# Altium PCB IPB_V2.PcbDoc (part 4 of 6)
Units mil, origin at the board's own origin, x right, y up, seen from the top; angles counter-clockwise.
Board outline 14000 x 12000 mil, 6 copper layers (Top, L2 - Plane/Horiz, L3 - Horiz, L4 - Vert, L5 - Plane/Horiz, Bottom), stack 61.468 mil thick; 657 components, 436 nets, 1897 pads, 873 vias.
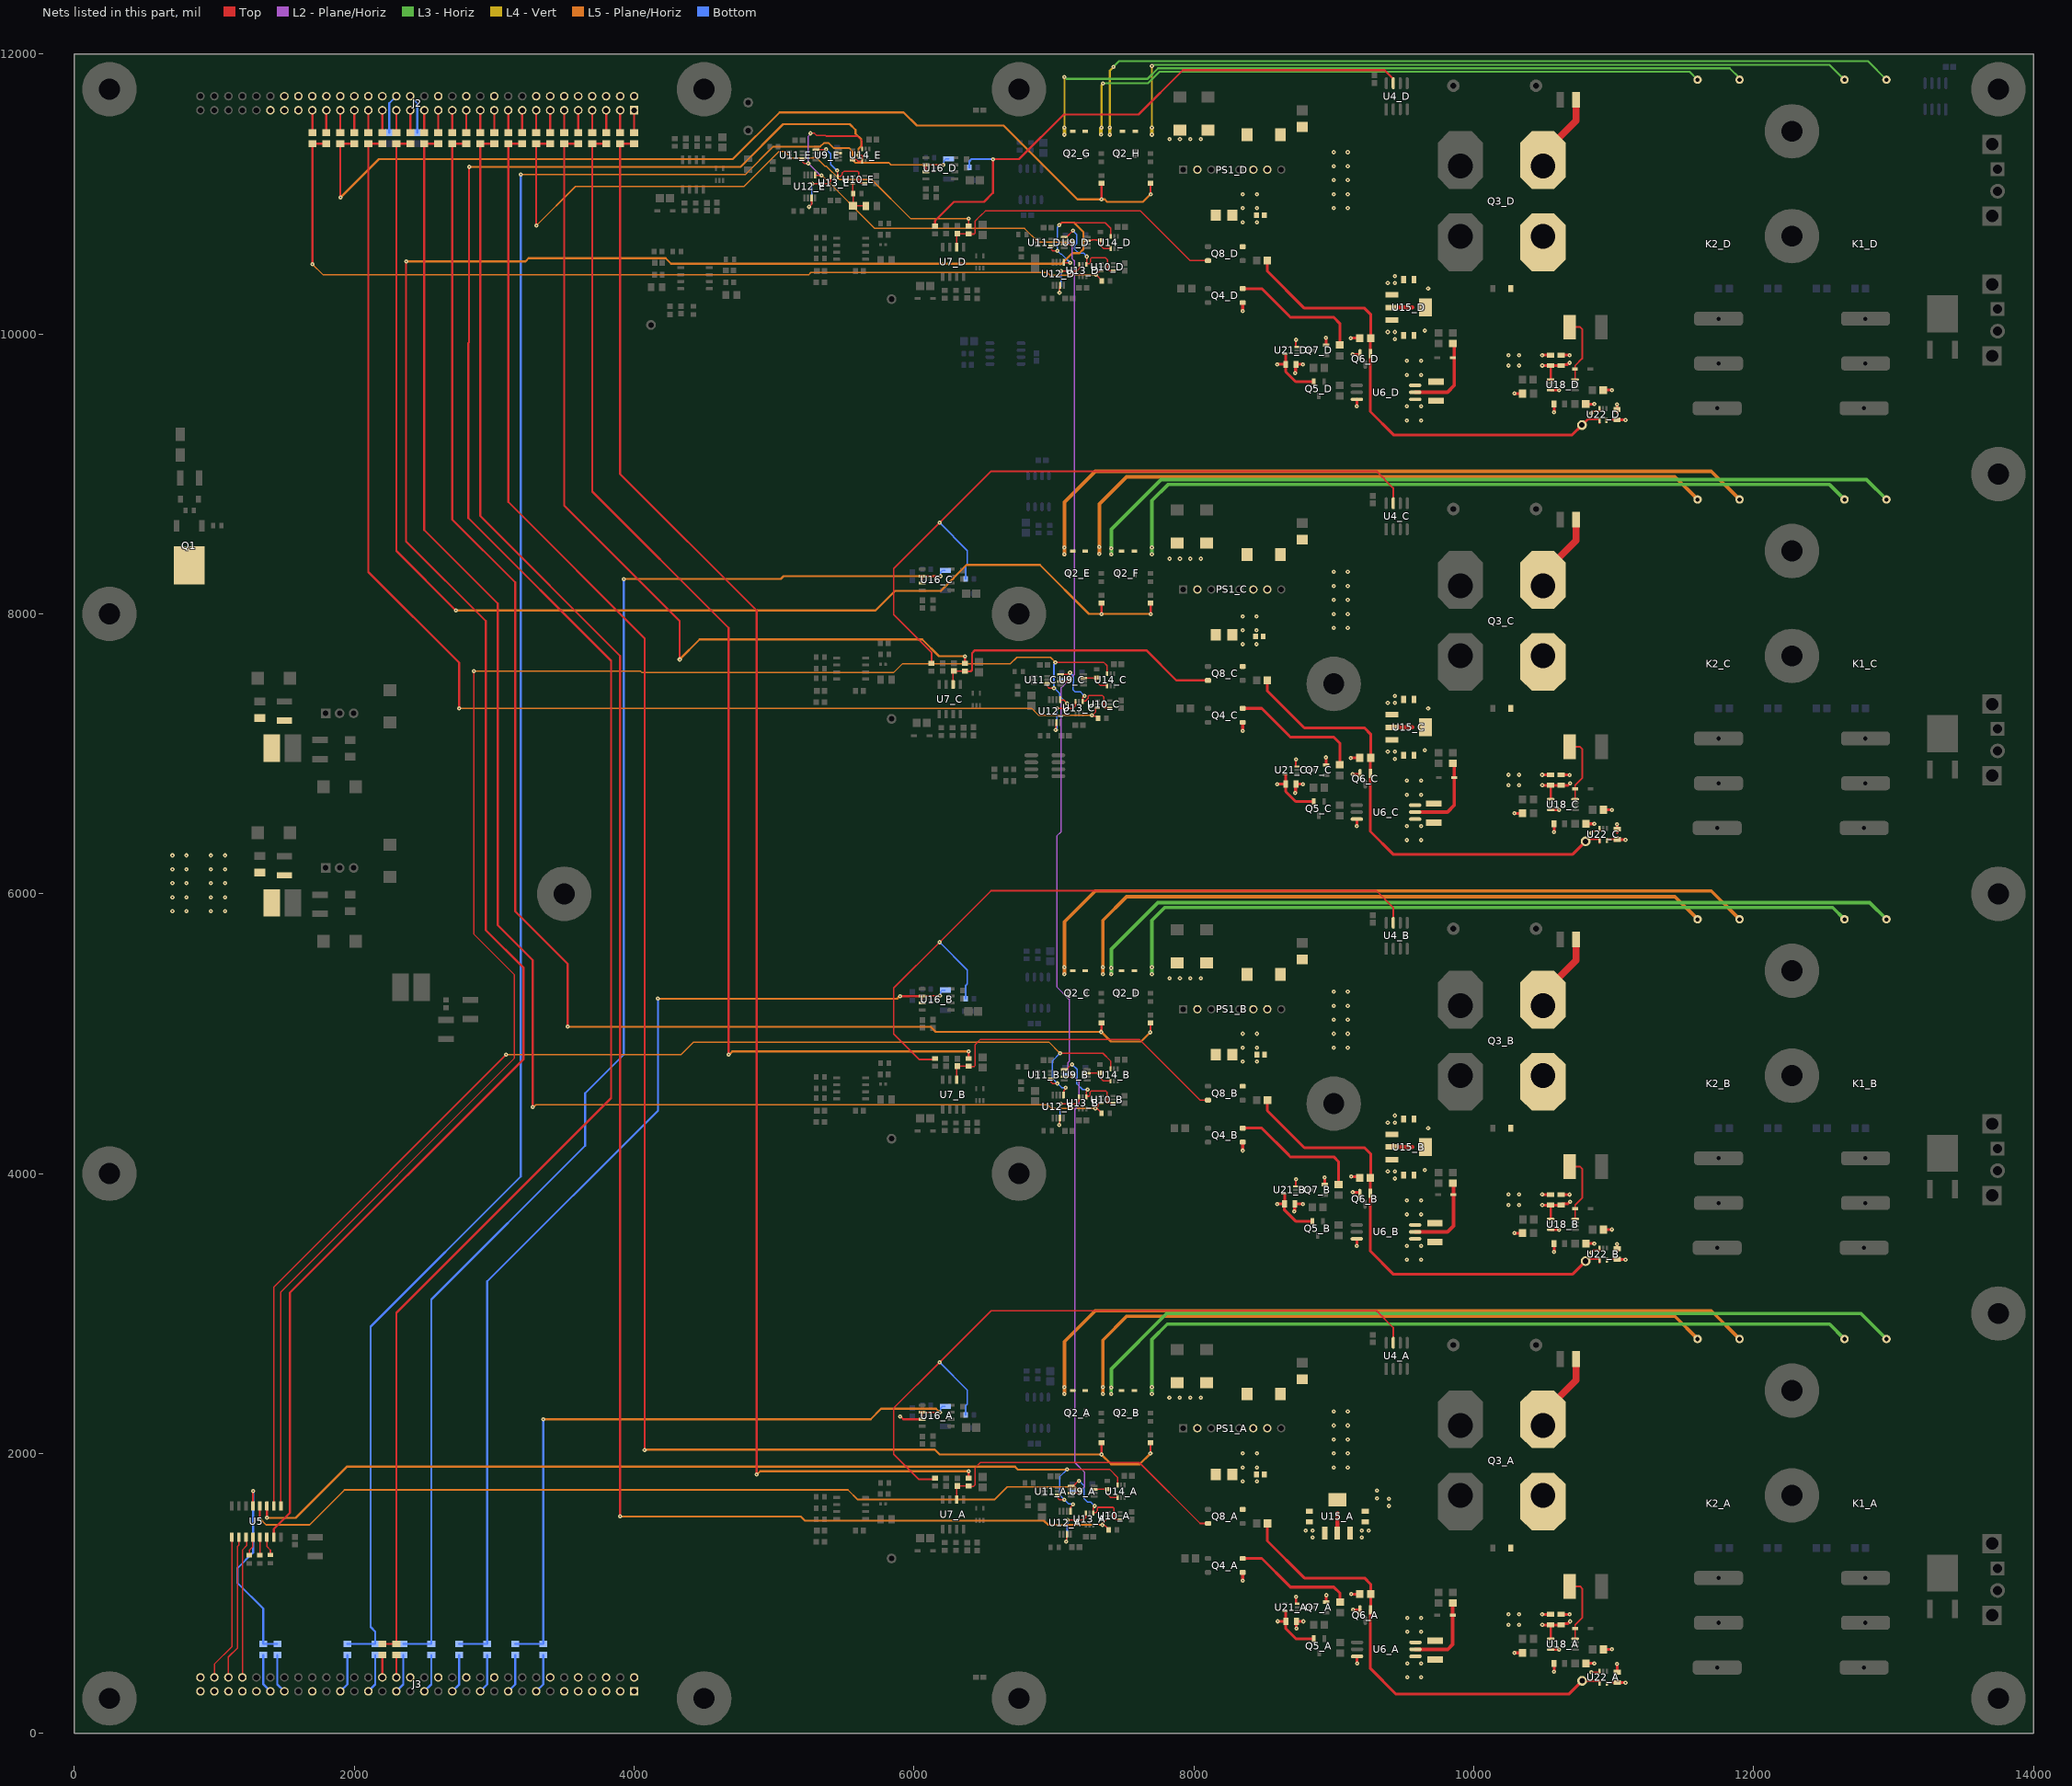
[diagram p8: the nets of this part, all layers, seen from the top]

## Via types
v1: diameter 30, hole 10, Top to Bottom, 873 vias

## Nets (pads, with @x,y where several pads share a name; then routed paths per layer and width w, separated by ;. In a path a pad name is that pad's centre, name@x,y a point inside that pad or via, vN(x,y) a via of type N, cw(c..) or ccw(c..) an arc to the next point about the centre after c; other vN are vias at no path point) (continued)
CH-EN_A: Q4_A.4 R92_A.1 | length 861.2
  Top w20: Q4_A.4@8349.02,1250 8485,1250 8680.03,1054.97 8690,1045 9000,1045 9045,1000 R92_A.1@9045,938.39
CH-EN_B: Q4_B.4 R92_B.1 | length 934.2
  Top w20: Q4_B.4@8349.02,4325 8485,4325 8680.03,4129.97 ; 8690,4120 9000,4120 9034.76,4085.24 R92_B.1@9034.76,3922.05
CH-EN_C: Q4_C.4 R92_C.1 | length 937.7
  Top w20: Q4_C.4@8349.02,7325 8485,7325 8680.03,7129.97 ; 8690,7120 9000,7120 9043.42,7076.58 R92_C.1@9043.42,6922.05
CH-EN_D: Q4_D.4 R92_D.1 | length 937.7
  Top w20: Q4_D.4@8349.02,10325 8485,10325 8680.03,10129.97 ; 8690,10120 9000,10120 9043.42,10076.58 R92_D.1@9043.42,9922.05
CH-ENABLE_E: C2.2 R42.1 R73_E.2 U10_E.3 | length 248.2
  Top w10: R73_E.2@5561.69,11011.22 U10_E.3@5561.69,11079.41 ; R73_E.2@5565.47,11005 5565.47,10916.89 C2.2@5565,10916.42 5654.21,10916.42 R42.1@5655.63,10915
CH-ENABLEBUF_A: U9_A.1 U10_A.4 U13_A.1 | length 661.3
  Top w10: U9_A.1@7123.31,1768.39 7139.06,1768.39 7175.67,1805 v1(7180,1805) ; U13_A.1@7280.59,1573.31 U13_A.1@7280.59,1575.13 ; v1(7290,1625) 7290,1619.59 7280.59,1610.18 7280.59,1580.87 7283.46,1578 7300,1578 7309,1587 7309,1609.14 7314.86,1615 7422.17,1615 7430,1607.17 7430,1535.32 7435.91,1529.41 U10_A.4@7473.31,1529.41
  Bottom w10: v1(7180,1805) 7215.32,1769.68 7215.32,1709.32 7213.99,1707.99 7213.99,1678.43 7238.8,1653.63 7261.37,1653.63 v1(7290,1625)
CH-ENABLEBUF_B: U9_B.1 U10_B.4 U13_B.1 | length 668.6
  Top w10: U9_B.1@7073.31,4743.39 7089.06,4743.39 7125.67,4780 v1(7130,4780) ; U13_B.1@7230.59,4548.31 U13_B.1@7230.59,4550.13 ; v1(7240,4600) 7240,4594.59 7230.59,4585.18 7230.59,4555.87 7233.46,4553 7250,4553 7259,4562 7259,4584.14 7264.86,4590 7372.17,4590 7380,4582.17 7380,4510.31 7385.91,4504.41 U10_B.4@7423.31,4504.41
  Bottom w10: v1(7130,4780) 7165.32,4744.68 7165.32,4684.32 7163.99,4682.99 7163.99,4641.01 7205,4600 v1(7240,4600)
CH-ENABLEBUF_C: U9_C.1 U10_C.4 U13_C.1 | length 646
  Top w10: U9_C.1@7048.31,7568.39 7097.97,7568.39 7109.59,7580 v1(7115,7580) ; U13_C.1@7205.59,7373.31 U13_C.1@7205.59,7375.13 ; v1(7218.42,7414.09) 7216.07,7414.09 7205.59,7403.62 7205.59,7380.87 7208.46,7378 7225,7378 7245,7398 7245,7412.14 7250.86,7418 7344.17,7418 7355,7407.17 7355,7335.32 7360.91,7329.41 U10_C.4@7398.31,7329.41
  Bottom w10: v1(7115,7580) 7140.32,7554.68 7140.32,7503.92 7135,7498.6 7135,7459.77 7152.93,7441.84 7190.68,7441.84 v1(7218.42,7414.09)
CH-ENABLEBUF_D: U9_D.1 U10_D.4 U13_D.1 | length 697.5
  Top w10: U9_D.1@7074.84,10693.39 7090.59,10693.39 7135,10737.79 v1(7135,10740) ; U13_D.1@7232.13,10498.31 U13_D.1@7232.13,10500.13 ; v1(7235.83,10554) 7233.98,10552.15 7233.98,10504.02 7235,10503 7251.54,10503 7260.54,10512 7260.54,10537.14 7269.39,10546 7367.7,10546 7381.54,10532.17 7381.54,10460.32 7387.44,10454.41 U10_D.4@7424.84,10454.41
  Bottom w10: v1(7135,10740) 7161.18,10713.82 7161.18,10645.21 7147.91,10631.95 7147.91,10607.09 7176.66,10578.35 7213.48,10578.35 7220.55,10571.28 7220.55,10569.28 v1(7235.83,10554)
CH-ENABLEBUF_E: U9_E.1 U10_E.4 U13_E.1 | length 593.1
  Top w10: U9_E.1@5298.31,11318.39 5299.11,11319.19 5372.07,11319.19 v1(5372.87,11320) ; v1(5449.14,11170) 5452.87,11166.26 5452.87,11133.59 5458.46,11128 5475,11128 5487.98,11140.98 5487.98,11152.33 5500.76,11165.12 5597.05,11165.12 5605,11157.17 5605,11085.32 5610.91,11079.41 U10_E.4@5648.31,11079.41
  Bottom w10: v1(5372.87,11320) 5405,11287.87 5405,11212.57 5447.57,11170 v1(5449.14,11170)
CH-ENABLEn_A: R74_A.2 U9_A.7 U14_A.1 | length 210.4
  Top w10: U9_A.7@7286.69,1742.8 7288.42,1744.53 7322.1,1744.53 7322.57,1745 7375.12,1745 7377.32,1742.8 7377.32,1712.72 7403.35,1686.69 U14_A.1@7454.41,1686.69
CH-ENABLEn_B: R74_B.2 U9_B.7 U14_B.1 | length 210.4
  Top w10: U9_B.7@7236.69,4717.8 7238.42,4719.53 7272.1,4719.53 7272.57,4720 7325.12,4720 7327.32,4717.8 7327.32,4687.72 7353.35,4661.69 U14_B.1@7404.41,4661.69
CH-ENABLEn_C: R74_C.2 U9_C.7 U14_C.1 | length 207.2
  Top w10: U9_C.7@7211.69,7542.8 R74_C.2@7302.32,7542.8 ; R74_C.2@7305,7545.47 7305,7515 7331.92,7488.08 7378.02,7488.08 U14_C.1@7379.41,7486.69
CH-ENABLEn_D: R74_D.2 U9_D.7 U14_D.1 | length 217.6
  Top w10: U9_D.7@7238.23,10667.8 7239.96,10669.53 7267.91,10669.53 7273.29,10674.92 7297.49,10674.92 7300.11,10672.29 7329.71,10672.29 R74_D.2@7331.54,10670.47 7331.54,10635.04 7354.88,10611.69 U14_D.1@7405.94,10611.69
CH-ENABLEn_E: U9_E.7
CH-I_A: R69_A.1 R79_A.1 U4_A.7 | length 5183.4
  Top w12: R69_A.1@6150,1822.56 6142.44,1815 6035,1815 5855,1995 5855,2325 v1(6182.13,2652.13) 6550,3020 9305,3020 9425,2900 U4_A.7@9425,2791.11
  Bottom w12: v1(6182.13,2652.13) 6381,2453.25 6381,2353.92 6369.68,2342.61 R79_A.1@6369.68,2275
CH-I_B: R69_B.1 R79_B.1 U4_B.7 | length 5210.3
  Top w12: R69_B.1@6150,4824.51 6142.44,4816.95 6035,4816.95 5855,4996.95 5855,5326.95 v1(6182.13,5654.07) 6550,6021.95 9305,6021.95 9425,5901.95 U4_B.7@9425,5793.06
  Bottom w12: v1(6182.13,5654.07) 6381,5455.2 6381,5355.87 6369.68,5344.55 R79_B.1@6369.68,5250
CH-I_C: R69_C.1 R79_C.1 U4_C.7 | length 5294.9
  Top w12: R69_C.1@6125,7647.56 6125,7725 5855,7995 5855,8325 v1(6182.13,8652.13) 6550,9020 9305,9020 9425,8900 U4_C.7@9425,8791.11
  Bottom w12: v1(6182.13,8652.13) 6381,8453.25 6381,8353.92 6369.68,8342.61 R79_C.1@6369.68,8250
CH-I_D: R69_D.1 R79_D.1 U4_D.7 | length 4177.1
  Top w15: R69_D.1@6150,10772.56 6150,10810 6285,10945 6500,10945 6565,11010 v1(6565,11250) 6750,11250 7070,11570 7605,11570 7921.32,11886.32 9362.98,11886.32 9425,11824.3 U4_D.7@9425,11793.06
  Bottom w15: R79_D.1@6394.68,11190 6394.68,11234.68 6410,11250 v1(6565,11250)
CHA_CURRENT_SET_1: R4.1 R6.1 R66_A.1 | length 11587.9
  Top w15: R4.1@4000,11360.63 R6.1@3900,11360.63 3900,9000 4875,8025 v1(4875,1850) ; R66_A.1@6390,1822.56 v1@6390,1872.09
  L5 - Plane/Horiz w15: v1(4875,1850) 4879.06,1850 4901.62,1872.56 v1(6389.53,1872.56)
CHA_FET_EN_1: R19.1 R21.1 R73_A.2 U10_A.3 | length 13919.3
  Top w10: U10_A.3@7386.69,1529.41 7376.85,1529.41 7349.12,1501.68 7349.12,1493.83 v1(7345.29,1490) 7349.12,1486.17 7363.24,1486.17 7390.47,1458.94 R73_A.2@7390.47,1455
  Top w15: R19.1@3000,11360.63 R21.1@2900,11360.63 2900,8700 3900,7700 v1(3900,1550)
  L5 - Plane/Horiz w15: v1(3900,1550) 5191.04,1550 5221.04,1520 6928.46,1520 6958.46,1490 v1(7345.29,1490)
CHA_I_1: C38_A.1 R20.1 R22.1 U16_A.6 U16_A.7 | length 5095.8
  Top w10: U16_A.7@6059.21,2245 U16_A.6@6059.21,2295 v1(6185,2295)
  Top w15: v1(5900,2265) 5904.06,2265 5924.06,2245 U16_A.7@6059.21,2245
  L5 - Plane/Horiz w15: v1(3350,2245) 5690,2245 5765,2320 6156.97,2320 6181.97,2295 v1(6185,2295)
  Bottom w10: v1(6185,2295) 6185,2297.71 6188.79,2301.5 6188.79,2323.03 6202.61,2336.85 C38_A.1@6223.28,2336.85
  Bottom w15: R22.1@3150,638.74 R20.1@3350,638.74 v1(3350,2245)
CHA_RLY_EN_1: R3.1 R5.1 R64_A.1 R64_B.1 | length 13693.8
  Top w15: R3.1@3200,11360.63 R5.1@3100,11360.63 3100,8800 4075,7825 v1(4075,2025) ; v1(7339,1993) 7339.5,1993.5 7339.5,2076.94 R64_A.1@7340,2077.44 ; v1(7690,2000) R64_B.1@7690,2077.44
  L5 - Plane/Horiz w15: v1(4075,2025) 4077.51,2027.51 6148.46,2027.51 6182.97,1993 v1(7339,1993) 7410,1922 7612,1922 v1(7690,2000)
CHB_CURRENT_SET_1: R8.1 R10.1 R66_B.1 | length 8787.9
  Top w15: R8.1@3800,11360.63 R10.1@3700,11360.63 3700,8875 4675,7900 v1(4675,4850) ; R66_B.1@6390,4822.56 v1@6390,4872.09
  L5 - Plane/Horiz w15: v1(4675,4850) 4679.06,4850 4701.62,4872.56 v1(6389.53,4872.56)
CHB_FET_EN_1: R23.1 R25.1 R73_B.2 U10_B.3 | length 11469.8
  Top w10: U10_B.3@7336.69,4504.41 7326.85,4504.41 7317.03,4494.59 7317.03,4486.11 v1(7295.81,4464.9) 7299.64,4461.08 7313.33,4461.08 7340.47,4433.94 R73_B.2@7340.47,4430
  Top w15: R23.1@2600,11360.63 R25.1@2500,11360.63 2500,8600 3025,8075 3025,5775 3275,5525 v1(3275,4475)
  L5 - Plane/Horiz w10: v1(3275,4475) 3280.41,4475 3297.91,4492.5 6955.07,4492.5 6982.67,4464.9 v1(7295.81,4464.9)
CHB_I_1: C38_B.1 R24.1 R26.1 U16_B.6 U16_B.7 | length 7461.6
  Top w10: U16_B.7@6059.21,5220 U16_B.6@6059.21,5270 v1(6185,5270)
  Top w15: v1(5900,5267.32) 5901.34,5268.66 6057.87,5268.66 U16_B.6@6059.21,5270
  L5 - Plane/Horiz w15: v1(4170,5250) 5878.62,5250 5895.94,5267.32 v1(5900,5267.32) v1@5898.66,5268.66
  Bottom w10: v1(6185,5270) 6185,5272.71 6188.79,5276.5 6188.79,5298.03 6202.61,5311.85 C38_B.1@6223.28,5311.85
  Bottom w15: R26.1@2750,638.74 R24.1@2950,638.74 2950,3230 4170,4450 v1(4170,5250)
CHB_RLY_EN_1: R7.1 R9.1 R64_C.1 R64_D.1 | length 11120.1
  Top w15: R7.1@2800,11360.63 R9.1@2700,11360.63 2700,8675 3150,8225 3150,5875 3525,5500 v1(3525,5050) ; v1(7338,5013) 7340,5015 R64_C.1@7340,5077.44 ; v1(7688,5010) 7690,5012 R64_D.1@7690,5077.44
  L5 - Plane/Horiz w15: v1(3525,5050) 6118.46,5050 6155.46,5013 v1(7338,5013) 7407,4944 7622,4944 v1(7688,5010)
CHC_CURRENT_SET_1: R12.1 R14.1 R66_C.1 | length 6325.1
  Top w15: R12.1@3600,11360.63 R14.1@3500,11360.63 3500,8775 4325,7950 v1(4325,7675) ; R66_C.1@6365,7647.56 v1@6365,7697.09
  L5 - Plane/Horiz w15: v1(4325,7675) 4467.5,7817.5 6058.61,7817.5 6178.55,7697.56 v1(6364.53,7697.56)
CHC_FET_EN_1: R27.1 R29.1 R73_C.2 U10_C.3 | length 9077.9
  Top w10: v1(7270,7275) v1@7272.87,7275 ; U10_C.3@7311.69,7329.41 7301.85,7329.41 7298.98,7326.54 7298.98,7301.11 v1@7272.87,7275 ; R73_C.2@7315.47,7255 7315.47,7258.94 7304.72,7269.69 7280.73,7269.69 7275.41,7275 v1@7272.87,7275
  Top w15: R27.1@2200,11360.63 R29.1@2100,11360.63 2100,8300 2750,7650 v1(2750,7325)
  L5 - Plane/Horiz w10: v1(2750,7325) 6842.43,7325 6892.43,7275 v1(7270,7275)
CHC_I_1: C38_C.1 R28.1 R30.1 U16_C.6 U16_C.7 | length 10901.9
  Top w10: U16_C.7@6059.21,8220 U16_C.6@6059.21,8270 v1(6190,8270)
  L5 - Plane/Horiz w15: v1(3925,8250) 5047.5,8250 5067.5,8270 v1(6190,8270)
  Bottom w10: v1(6190,8270) 6190,8298.03 6203.82,8311.85 C38_C.1@6223.28,8311.85
  Bottom w15: R30.1@2350,638.74 R28.1@2550,638.74 2550,3100 3650,4200 3650,4575 3925,4850 v1(3925,8250)
CHC_RLY_EN_1: R11.1 R13.1 R64_E.1 R64_F.1 | length 9014
  Top w15: R11.1@2400,11360.63 R13.1@2300,11360.63 2300,8450 v1(2725,8025) ; v1(7340,8000) R64_E.1@7340,8077.44 ; R64_F.1@7690,8077.44 7691,8076.44 7691,8001 v1(7692,8000)
  L5 - Plane/Horiz w15: v1(2725,8025) 5725,8025 5865,8165 6190.96,8165 6375.96,8350 6900,8350 7250,8000 v1(7340,8000) v1(7692,8000)
CHD_CURRENT_SET_1: R16.1 R18.1 R66_D.1 | length 4244.8
  Top w10: R66_D.1@6390,10772.56 v1(6390,10824.22)
  Top w15: v1(3300,10775) R18.1@3300,11360.63 R16.1@3400,11360.63
  L5 - Plane/Horiz w10: v1(3300,10775) 3580,11055 4785,11055 5033.55,11303.55 5079.51,11303.55 5123.06,11260 5302.57,11260 5362.57,11200 5373.43,11200 5468.1,11105.33 5512.15,11105.33 5512.37,11105.12 5697.31,11105.12 5978.21,10824.22 v1(6390,10824.22)
CHD_FET_EN_1: R31.1 R34.1 R73_D.2 U10_D.3 | length 6722.2
  Top w10: U10_D.3@7338.23,10454.41 7328.39,10454.41 7300,10426.02 v1(7300,10425) 7300.94,10425 7342.01,10383.94 R73_D.2@7342.01,10380
  Top w15: v1(1700,10500) R34.1@1700,11360.63 R31.1@1800,11360.63
  L5 - Plane/Horiz w10: v1(1700,10500) 1775,10425 5248.33,10425 5263.34,10440 6952.57,10440 6972.57,10420 7094.27,10420 7099.27,10425 v1(7300,10425)
CHD_I_1: C38_D.1 R32.1 R35.1 U16_D.6 U16_D.7 | length 14618
  Top w10: U16_D.7@6084.21,11160 U16_D.6@6084.21,11210 v1(6210,11210)
  L5 - Plane/Horiz w12: v1(3190,11140) 4795,11140 4995,11340 5330,11340 5355,11365 5390,11365 5425,11330 5535,11330 5560,11305 5560,11245 5580,11225 5820,11225 5835,11210 v1(6210,11210)
  Bottom w10: v1(6210,11210) 6210,11212.71 6213.79,11216.5 6213.79,11238.03 6227.61,11251.85 C38_D.1@6248.28,11251.85
  Bottom w15: R35.1@1950,638.74 R32.1@2150,638.74 2150,726.21 2116.46,759.75 2116.46,2906.46 3190,3980 v1(3190,11140)
CHD_RLY_EN_1: R15.1 R17.1 R64_G.1 R64_H.1 | length 7008.2
  Top w15: v1(1900,10975) R17.1@1900,11360.63 R15.1@2000,11360.63 ; R64_G.1@7340,11077.44 7340.5,11076.94 7340.5,10963.5 v1(7341,10963) ; v1@7690.5,11001.5 R64_H.1@7690.5,11076.94
  L5 - Plane/Horiz w15: v1(1900,10975) 2175,11250 4705,11250 5040,11585 5925,11585 6020,11490 6640,11490 7167,10963 v1(7341,10963) 7341.66,10962.34 7362.66,10962.34 7380,10945 7636,10945 v1(7691.5,11000.5)
COIL_DRV_HIGH_A: C16_A.1 C16_B.1 C16_C.1 C16_D.1 C17_A.2 C17_B.2 C17_C.2 C17_D.2 C18_A.2 C18_B.2 C18_C.2 C18_D.2 C45.2 C55.2 D4_A.1 D4_B.1 D4_C.1 D4_D.1 D4_E.1 D4_F.1 D4_G.1 D4_H.1 K1_A.2 K1_B.2 K1_C.2 K1_D.2 K2_A.2 K2_B.2 K2_C.2 K2_D.2 L2.1 L4.1 PS1_A.2 PS1_B.2 PS1_C.2 PS1_D.2 Q1.2 R81.2 R85.2 | length 45321.5
  L3 - Horiz w15: v1(7075,11836.21) 7079.06,11836.21 7090.27,11825 7669.64,11825 7744.64,11900 11830,11900 11900,11830 K2_D.2@11900,11818 ; v1(7424.16,11908.81) 7465.36,11950 12818,11950 K1_D.2@12950,11818
  L3 - Horiz w25: v1(7409.58,2425.42) 7409.79,2425.63 7409.79,2469.79 v1(7410,2470) 7410,2605 7805,3000 12768,3000 K1_A.2@12950,2818 ; v1(7409.86,5425.07) 7409.86,5604.86 7742.2,5937.2 12830.8,5937.2 K1_B.2@12950,5818 ; v1(7410,8425) v1(7410,8470) 7409.86,8470.14 7409.86,8604.86 7765,8960 12808,8960 K1_C.2@12950,8818
  L5 - Plane/Horiz w25: v1(7075,2425) v1(7075,2475) 7075,2800 7295,3020 11698,3020 K2_A.2@11900,2818 ; v1(7075,5425) v1(7075,5475) 7075,5800 7295,6020 11698,6020 K2_B.2@11900,5818 ; v1(7075,8425) v1(7075,8475) 7075,8800 7295,9020 11698,9020 K2_C.2@11900,8818
  L4 - Vert w15: v1(7075,11475) v1(7075,11836.21) ; v1(7398.66,11476.26) 7398.66,11881.27 7424.16,11906.77 v1(7424.16,11908.81)
  L4 - Vert w25: v1(7075,11425) v1(7075,11475) ; v1(7398.66,11476.26) 7399.33,11475.59 7399.33,11425.67 v1(7400,11425)
  other v1: 7825,2400 7900,2400 7975,2400 8050,2400 7825.39,5394.88 7900.39,5394.88 7975.39,5394.88 8050.39,5394.88 7409.86,5470 700,5875 800,5875 975,5875 1075,5875 700,5975 800,5975 975,5975 1075,5975 700,6075 800,6075 975,6075 1075,6075 700,6175 800,6175 975,6175 1075,6175 700,6275 800,6275 975,6275 1075,6275 7825.39,8394.88 7900.39,8394.88 7975.39,8394.88 8050.39,8394.88 7825.39,11394.88 7900.39,11394.88 7975.39,11394.88 8050.39,11394.88
COIL_RTN_HIGH_A: D4_B.2 K1_A.5 Q2_B.2 | length 5429.9
  L3 - Horiz w25: v1(7700,2425) v1(7700,2475) 7700,2815 7810,2925 12543,2925 K1_A.5@12650,2818
COIL_RTN_HIGH_B: D4_D.2 K1_B.5 Q2_D.2 | length 5408.1
  L3 - Horiz w25: v1(7700,5425) v1(7700,5475) 7700,5810 7792.2,5902.2 12565.8,5902.2 K1_B.5@12650,5818
COIL_RTN_HIGH_C: D4_F.2 K1_C.5 Q2_F.2 | length 5427
  L3 - Horiz w25: v1(7700,8425) v1(7700,8475) 7700,8810 7815,8925 12543,8925 K1_C.5@12650,8818
COIL_RTN_HIGH_D: D4_H.2 K1_D.5 Q2_H.2 | length 5489.9
  L3 - Horiz w15: v1(7700,11917.5) 7704.06,11917.5 7711.56,11925 12543,11925 K1_D.5@12650,11818
  L4 - Vert w15: v1(7700,11475) v1(7700,11917.5)
  L4 - Vert w25: v1(7700,11425) v1(7700,11475)
COIL_RTN_LOW_A: D4_A.2 K2_A.5 Q2_A.2 | length 4772.5
  L5 - Plane/Horiz w25: v1(7350,2425) v1(7350,2475) 7350,2810 7520,2980 11438,2980 K2_A.5@11600,2818
COIL_RTN_LOW_B: D4_C.2 K2_B.5 Q2_C.2 | length 4772.5
  L5 - Plane/Horiz w25: v1(7350,5425) v1(7350,5475) 7350,5810 7520,5980 11438,5980 K2_B.5@11600,5818
COIL_RTN_LOW_C: D4_E.2 K2_C.5 Q2_E.2 | length 4777.9
  L5 - Plane/Horiz w25: v1(7325,8429.97) 7325,8785 7520,8980 11438,8980 K2_C.5@11600,8818
  other v1: 7325,8479.97
COIL_RTN_LOW_D: D4_G.2 K2_D.5 Q2_G.2 | length 4680.1
  L3 - Horiz w15: v1(7350,11792.5) 7672.5,11792.5 7755,11875 11543,11875 K2_D.5@11600,11818
  L4 - Vert w15: v1(7339.53,11475) 7339.53,11777.97 7350,11788.44 v1(7350,11792.5)
  L4 - Vert w25: v1(7335.96,11425.96) 7335.96,11470.08 7339.53,11473.65 v1(7339.53,11475)
DIO_SPARE_0_3: J2.2
DIO_SPARE_1_3: J2.4
DIO_SPARE_2_3: J2.6
DIO_SPARE_3_3: J2.8
DIO_SPARE_4_3: J2.10
DIO_SPARE_5_3: J2.12
DIO_SPARE_6_3: J2.14
DIO_SPARE_7_3: J2.16
FAULT-BUF_A: Q6_A.1 R83_A.2 R90_A.2 TP5_A.1 U22_A.4 | length 3358.4
  Top w15: TP5_A.1@10775,375 10898.78,375 10899.41,374.37 U22_A.4@10899.41,364.53
  Top w20: R83_A.2@8526.77,1500 8525,1498.23 8525,1375 8790,1110 9220,1110 9263.39,1066.61 R90_A.2@9263.39,995 9262.89,994.51 9262.89,883.9 Q6_A.1@9262.4,883.4 9262.4,462.6 9445,280 10680,280 TP5_A.1@10775,375
FAULT-BUF_B: Q6_B.1 R83_B.2 R90_B.2 TP5_B.1 U22_B.4 | length 3415.1
  Top w15: TP5_B.1@10800,3375 10812.67,3375 10827.67,3390 10898.78,3390 10898.78,3365.36 U22_B.4@10899.41,3364.72
  Top w20: R83_B.2@8525,4525 8525,4450 8790,4185 9220,4185 9263.39,4141.61 9263.39,3971.58 R90_B.2@9261.81,3970 ; R90_B.2@9261.32,3970 9261.32,3867.56 9260.83,3867.07 9260.83,3446.26 9426.89,3280.2 10705.2,3280.2 TP5_B.1@10800,3375
FAULT-BUF_C: Q6_C.1 R83_C.2 R90_C.2 TP5_C.1 U22_C.4 | length 3415.1
  Top w15: TP5_C.1@10800,6375 10812.67,6375 10827.67,6390 10898.78,6390 10898.78,6365.36 U22_C.4@10899.41,6364.72
  Top w20: R83_C.2@8525,7525 8525,7450 8790,7185 9220,7185 9263.39,7141.61 R90_C.2@9263.39,6971.58 R90_C.2@9261.81,6970 ; R90_C.2@9261.32,6970 9261.32,6867.56 9260.83,6867.07 9260.83,6446.26 9426.89,6280.2 10705.2,6280.2 TP5_C.1@10800,6375
FAULT-BUF_D: Q6_D.1 R83_D.2 R90_D.2 TP5_D.1 U22_D.4 | length 3413.5
  Top w15: TP5_D.1@10774.49,9349.49 10815,9390 10897.75,9390 10897.75,9366.38 U22_D.4@10898.78,9365.36
  Top w20: R83_D.2@8525,10525 8525,10450 8790,10185 9220,10185 9263.39,10141.61 R90_D.2@9263.39,9971.58 R90_D.2@9261.81,9970 ; R90_D.2@9261.32,9970 9261.32,9867.56 9260.83,9867.07 9260.83,9446.26 9427.09,9280 10703.98,9280 TP5_D.1@10773.98,9350
FAULT-INJECT_A: C24_A.1 Q8_A.4 R66_A.2 U7_A.2 | length 2215.4
  Top w10: U7_A.2@6305,1668.35 6305,1763.43 C24_A.1@6310,1768.43 6310.98,1767.44 R66_A.2@6390,1767.44 6392.44,1765 6425,1765 6435,1775 6435,1895 6475,1935 7610,1935 8045,1500 Q8_A.4@8100.98,1500
FAULT-INJECT_B: C24_B.1 Q8_B.4 R66_B.2 U7_B.2 | length 2242.9
  Top w10: U7_B.2@6305,4668.35 6305,4763.43 C24_B.1@6310,4768.43 6310.98,4767.44 R66_B.2@6390,4767.44 6392.44,4765 6429.14,4765 6435,4770.86 6435,4920 6475,4960 7610,4960 8045,4525 Q8_B.4@8100.98,4525
FAULT-INJECT_C: C24_C.1 Q8_C.4 R66_C.2 U7_C.2 | length 2141
  Top w10: U7_C.2@6280,7493.35 6280,7588.43 C24_C.1@6285,7593.43 6285.98,7592.44 R66_C.2@6365,7592.44
  Top w15: R66_C.2@6365,7592.44 6367.44,7590 6405,7590 6415,7600 6415,7720 6435,7740 7660,7740 7875,7525 Q8_C.4@8100.98,7525
FAULT-INJECT_D: C24_D.1 Q8_D.4 R66_D.2 U7_D.2 | length 2159.6
  Top w10: U7_D.2@6305,10618.35 6305,10713.43 C24_D.1@6310,10718.43 6310.98,10717.44 R66_D.2@6390,10717.44 6392.44,10715 6429.14,10715 6435,10720.86 6435,10805.7 6474.89,10845.59 6475.59,10845.59 6510,10880 7620,10880 7975,10525 Q8_D.4@8100.98,10525
FAULT_MUX_A: J3.58 U5.11 | length 1017.1
  Top w10: J3.58@1200,400 1200,1310 1230,1340 1230,1397.56 U5.11@1225,1402.56
FAULT_MUX_B: J3.60 U5.10 | length 1033.6
  Top w10: J3.60@1100,400 1100,545 1165,610 1165,1335 1175,1345 U5.10@1175,1402.56
FAULT_MUX_C: J3.62 U5.9 | length 1054.3
  Top w10: J3.62@1000,400 1000,495 1125,620 U5.9@1125,1402.56
FAULT_SENSE: R39.1 R40.1 U5.5 | length 1423.8
  Top w15: U5.5@1275,1625 1275.47,1625.47 1275.47,1731.81 v1(1275.94,1732.28)
  Bottom w15: v1(1275.94,1732.28) 1275.94,1290.94 1165,1180 1165,1075 1350,890 R40.1@1350,638.74 R39.1@1450,638.74
FAULT_SENSE_HCB_3: J3.55
FAULT_SENSE_IN0: R70_A.2 R70_B.2 R70_C.2 R70_D.2 U5.4 U9_A.3 U9_B.3 U9_C.3 U9_D.3 U11_E.4 U12_E.1 U14_E.6 | length 18671
  Top w10: U11_E.4@5203.23,11254.41 5203.23,11231.77 5215,11220 v1(5245,11220) ; v1(5260,11434.84) 5288.11,11434.84 5302.08,11420.87 5366.79,11420.87 5372.66,11415 5595,11415 5629.41,11380.59 U14_E.6@5629.41,11323.31 ; U12_E.1@5293.39,11136.69 5295.08,11135 v1(5340,11135) ; U9_C.3@7048.31,7517.2 7092.11,7517.2 7104.9,7530 v1(7110.32,7530) ; U9_B.3@7073.31,4692.2 7117.11,4692.2 7129.9,4705 v1(7135.32,4705) ; U9_D.3@7074.84,10642.2 7116.03,10642.2 7131.18,10657.35 v1(7131.18,10657.64) ; U9_A.3@7123.31,1717.2 7167.11,1717.2 7179.9,1730 v1(7185.32,1730)
  Top w15: v1(1325,1535) U5.4@1325,1625
  L2 - Plane/Horiz w10: v1(5260,11434.84) 5260,11429.43 5245,11414.43 v1(5245,11220) 5326.17,11138.83 5336.17,11138.83 v1(5340,11135) ; v1(7131.18,10657.64) 7131.18,10537.78 7146.54,10522.43 7146.54,7566.22 v1(7110.32,7530) 7052.2,7471.89 7052.2,6444.7 7020,6412.5 7020,5335 7110,5245 7110,4802.57 7100,4792.57 7100,4740.32 v1(7135.32,4705) 7180,4660.32 7180,4490 7150,4460 7150,1935 7220,1865 7220,1764.68 v1(7185.32,1730)
  L5 - Plane/Horiz w10: v1(5340,11135) 5720,10755 6790,10755 6887.36,10657.64 v1(7131.18,10657.64)
  L5 - Plane/Horiz w12: v1(1325,1535) 1370,1490 1680,1490 1930,1740 5527.77,1740 5597.77,1670 6575,1670 6666,1761 7154.32,1761 v1(7185.32,1730)
  L4 - Vert w10: v1@7105,7530 v1(7110.32,7530) v1@7110.32,7528.04
  Bottom w10: R70_C.2@7055,7525.47 7097.77,7525.47 7098.47,7526.17 7106.49,7526.17 v1(7110.32,7530) ; R70_B.2@7080,4700.47 7122.77,4700.47 7123.47,4701.17 7131.49,4701.17 v1(7135.32,4705) ; R70_D.2@7081.54,10650.47 7118.6,10650.47 7125.77,10657.64 v1(7131.18,10657.64) ; R70_A.2@7130,1725.47 7172.77,1725.47 7173.47,1726.17 7181.49,1726.17 v1(7185.32,1730)
FAULT_SENSE_IN1: U5.3 U11_A.4 U12_A.1 U14_A.6 | length 6860.7
  Top w10: U11_A.4@7028.23,1704.41 7028.23,1681.77 7040,1670 v1(7075,1670) ; v1(7093.19,1884.78) 7400.22,1884.78 7454.41,1830.59 U14_A.6@7454.41,1773.31 ; U12_A.1@7118.39,1586.69 7120.64,1588.94 7120.64,1617.98 7135,1632.34 v1(7135,1637.76)
  Top w15: v1(1375,1540) U5.3@1375,1625
  L5 - Plane/Horiz w15: v1(1375,1540) 1580,1540 1945.06,1905.06 6722.46,1905.06 6742.74,1884.78 v1(7093.19,1884.78)
  Bottom w10: v1(7093.19,1884.78) 7040,1831.59 7040,1705 v1(7075,1670) 7105,1640 7132.76,1640 v1(7135,1637.76)
FAULT_SENSE_IN2: U5.2 U11_B.4 U12_B.1 U14_B.6 | length 8839.1
  Top w10: U5.2@1425,1625 1425,3190 v1(3085,4850) ; U11_B.4@6978.23,4679.41 6978.23,4656.77 6990,4645 v1(7025,4645) ; v1(7043.19,4859.78) 7350.22,4859.78 7404.41,4805.59 U14_B.6@7404.41,4748.31 ; U12_B.1@7068.39,4561.69 7070.64,4563.94 7070.64,4592.98 7085,4607.34 v1(7085,4612.76)
  L5 - Plane/Horiz w10: v1(3085,4850) 4335,4850 4425,4940 6962.98,4940 v1(7043.19,4859.78)
  Bottom w10: v1(7043.19,4859.78) 6990,4806.59 6990,4680 v1(7025,4645) 7055,4615 7082.76,4615 v1(7085,4612.76)
FAULT_SENSE_IN3: U5.1 U11_C.4 U12_C.1 U14_C.6 | length 11945.1
  Top w10: U5.1@1475,1625 1475,3155 3145,4825 3145,5420 2855,5710 v1(2855,7590) ; U11_C.4@6953.23,7504.41 6953.23,7481.77 6965,7470 v1(7000,7470) ; v1(7010,7655) 7355,7655 7379.41,7630.59 U14_C.6@7379.41,7573.31 ; U12_C.1@7043.39,7386.69 7045.55,7386.69 7047.24,7385 7070,7385 v1(7095,7360)
  L5 - Plane/Horiz w10: v1(2855,7590) 4046.42,7590 4056.42,7580 5853.96,7580 5918.96,7645 6690,7645 6735,7690 6975,7690 v1(7010,7655) ; 7070,7385 v1(7095,7360)
  Bottom w10: v1(7000,7470) 7000,7639.59 7010,7649.59 v1(7010,7655) ; v1@7000.09,7470.09 7002.48,7470.09 7039.69,7432.89 7039.69,7415.31 v1(7095,7360)
FAULT_SENSE_IN4: U5.15 U11_D.4 U12_D.1 U14_D.6 | length 16332.6
  Top w10: U11_D.4@6979.76,10629.41 6979.76,10606.77 6991.54,10595 v1(7025,10595) ; v1(7036.54,10780) 7039.78,10780 7054.78,10795 7366.54,10795 7405.94,10755.59 U14_D.6@7405.94,10698.31 ; U12_D.1@7069.92,10511.69 7071.61,10510 v1(7116.54,10510)
  Top w15: U5.15@1425,1402.56 1425,1460 1540,1575 1540,3150 3210,4820 3210,5470 2940,5740 2940,7948.79 2370,8518.79 v1(2370,10520)
  L5 - Plane/Horiz w15: v1(2370,10520) 3223.28,10520 3245.78,10542.5 4224.62,10542.5 4264.62,10502.5 7056,10502.5 7131.62,10578.12 7182.47,10578.12 7210.41,10606.06 7210.41,10729.59 7142.5,10797.5 7058.09,10797.5 7040.59,10780 v1(7036.54,10780)
  Bottom w10: v1(7036.54,10780) 7036.54,10774.59 7025,10763.05 v1(7025,10595) 7046.48,10573.52 7053.02,10573.52 v1(7116.54,10510)
FAULT_SENSE_IN5: R97.2 U5.14 | length 138.4
  Top w10: U5.14@1375,1402.56 1375,1334.96 1400,1309.96 R97.2@1400,1274.53
FAULT_SENSE_IN6: R96.2 U5.13 | length 128.5
  Top w10: R96.2@1325,1274.05 U5.13@1325,1402.56
FAULT_SENSE_IN7: R95.2 U5.12 | length 138.9
  Top w10: R95.2@1250,1274.05 1250,1309.49 1275,1334.49 U5.12@1275,1402.56
FAULT_SENSE_IPB1_3: J3.51 R39.2 | length 280.7
  Bottom w15: R39.2@1450,560 1450,350 J3.51@1500,300
FAULT_SENSE_IPB2_3: J3.53 R40.2 | length 280.7
  Bottom w15: R40.2@1350,560 1350,350 J3.53@1400,300
GATE_DRV_HIGH_A: D7_A.2 R91_A.1 U6_A.5 | length 577.5
  Top w25: U6_A.5@9583.66,600 9815,600 9850,635 D7_A.2@9850,845 R91_A.1@9850,931.61
GATE_DRV_HIGH_B: D7_B.2 R91_B.1 U6_B.5 | length 590.6
  Top w25: U6_B.5@9582.09,3583.66 9812.05,3583.66 9855.12,3626.73 R91_B.1@9855.12,3926.5
GATE_DRV_HIGH_C: D7_C.2 R91_C.1 U6_C.5 | length 602.1
  Top w25: U6_C.5@9582.09,6583.66 9812.05,6583.66 9860.24,6631.85 9860.24,6921.38 R91_C.1@9850,6931.61
GATE_DRV_HIGH_D: D7_D.2 R91_D.1 U6_D.5 | length 587.6
  Top w25: U6_D.5@9582.09,9583.66 9812.05,9583.66 9860.24,9631.85 R91_D.1@9860.24,9921.38
GF_AMP_TEMP_F_3: J3.59
GF_ANNODE_SEL_EN_3: J3.9
GF_CHASSIS_SEL_EN_3: J3.11
GF_SIG_3: J3.47
GF_SOURCE_SEL_A_3: J3.1
GF_SOURCE_SEL_B_3: J3.3
GF_SOURCE_SEL_C_3: J3.5
GF_SOURCE_SEL_EN_3: J3.7
HAS-FAULTEDn_A: U12_A.7 U13_A.3 | length 381.1
  Top w10: v1(7088.07,1371.34) 7091.06,1374.33 7091.06,1421.57 U12_A.7@7092.8,1423.31 ; v1(7097.2,1525) 7211,1525 7229.41,1543.41 U13_A.3@7229.41,1573.31
  Bottom w10: v1(7088.07,1371.34) 7090.29,1373.56 7090.29,1401.34 7095.3,1406.34 7095.3,1523.09 v1(7097.2,1525)
HAS-FAULTEDn_B: U12_B.7 U13_B.3 | length 381.1
  Top w10: v1(7038.07,4346.34) 7041.06,4349.33 7041.06,4396.57 U12_B.7@7042.8,4398.31 ; v1(7047.2,4500) 7161,4500 7179.41,4518.41 U13_B.3@7179.41,4548.31
  Bottom w10: v1(7038.07,4346.34) 7040.29,4348.56 7040.29,4376.34 7045.3,4381.34 7045.3,4498.09 v1(7047.2,4500)
HAS-FAULTEDn_C: U12_C.7 U13_C.3 | length 381.6
  Top w10: v1(7013.07,7171.34) 7016.06,7174.33 7016.06,7221.57 U12_C.7@7017.8,7223.31 ; v1(7022.2,7325) 7136,7325 7154.41,7343.41 U13_C.3@7154.41,7373.31
  Bottom w10: v1(7013.07,7171.34) 7013.07,7176.75 7022.81,7186.49 7022.81,7324.39 v1(7022.2,7325)
HAS-FAULTEDn_D: U12_D.7 U13_D.3 | length 380.4
  Top w10: v1(7039.61,10296.34) 7042.6,10299.33 7042.6,10346.57 U12_D.7@7044.33,10348.31 ; v1(7050,10450) 7162.54,10450 7180.94,10468.41 U13_D.3@7180.94,10498.31
  Bottom w10: v1(7039.61,10296.34) 7039.61,10326.81 7050,10337.2 v1(7050,10450)
HAS-FAULTEDn_E: U12_E.7 U13_E.3 | length 416.5
  Top w10: v1(5250.36,10909) 5268.09,10926.73 5268.09,10973.01 U12_E.7@5267.8,10973.31 ; v1(5272.2,11075) 5386,11075 5404.41,11093.41 U13_E.3@5404.41,11123.31
  Bottom w10: v1(5250.36,10909) 5250.36,10911.56 5270.3,10931.5 5270.3,11073.09 v1(5272.2,11075)
HCB_MEDIA_EN_3: J2.30
HPB_5V_CURRENT_3: J3.34
HPB_5V_VOLTAGE_3: J3.30
HPB_24V_CURRENT_3: J3.26
HPB_24V_VOLTAGE_3: J3.22
HPB_CISCO1_CURRENT_3: J3.2
HPB_CISCO1_EN_3: J2.49
HPB_CISCO2_CURRENT_3: J3.6
HPB_CISCO2_EN_3: J2.51
HPB_ISO24V_CURRENT_3: J3.14
HPB_MEDIA_CURRENT_3: J3.64
HPB_SYNCBOX_CURRENT_3: J3.10
HPB_SYNCBOX_EN_3: J2.53
HPB_TEMP0_3: J2.44
HPB_TEMP1_3: J2.46
HPB_TEMP2_3: J2.48
HPB_TEMP3_3: J2.50
HPB_TEMP4_3: J2.52
HPB_VICOR1_TEMP_3: J2.38
HPB_VICOR2_TEMP_3: J2.40
HPB_VICOR3_TEMP_3: J2.42
HV_P5V_A: C47_A.2 C49_A.2 C50_A.2 C51_A.2 C61_A.2 Q5_A.2 R62_A.2 R93_A.2 U15_A.3 U18_A.1 U21_A.5 U22_A.5 | length 982.1
  Top w15: U18_A.1@10550,675.59 C49_A.2@10550,775 ; U22_A.5@10950.59,364.53 10950.59,363.23 10951.22,362.6 C61_A.2@11025,362.6
  Top w20: v1@8597.8,800 C51_A.2@8657.6,800 ; U21_A.5@8659.53,874.41 8659.41,874.41 8657.6,872.6 C51_A.2@8657.6,800 ; Q5_A.2@8857.6,676.18 8728.82,676.18 8657.6,747.4 C51_A.2@8657.6,800 ; v1@10490.2,775 C49_A.2@10550,775 C50_A.2@10625,775 10632.72,782.72 10670.01,782.72 10687.29,800 v1(10690,800) ; R62_A.2@10801.77,500 v1@10861.57,500 ; R93_A.2@10926.77,600 v1@10986.57,600 ; C61_A.2@11025,362.6 v1@11084.8,362.6
  other v1: 11084.9,362.5 10861.67,499.9 10986.67,599.9 10490.1,775.1 8597.7,800.1 9200,1400 9200,1450 9250,1450
HV_P5V_B: C47_B.2 C49_B.2 C50_B.2 C51_B.2 C61_B.2 Q5_B.2 R62_B.2 R93_B.2 U15_B.3 U18_B.1 U21_B.5 U22_B.5 | length 960.2
  Top w15: U18_B.1@10550,3675.79 C49_B.2@10550,3775.2 ; U22_B.5@10950.59,3389.53 11006.91,3389.53 11008.66,3387.77 C61_B.2@11008.66,3379.13
  Top w20: v1@8596.22,3783.66 C51_B.2@8647.36,3783.66 8647.36,3739.72 8727.24,3659.84 Q5_B.2@8847.36,3659.84 ; C51_B.2@8649.29,3783.66 U21_B.5@8649.29,3858.07 ; v1@10490.2,3775.2 C49_B.2@10550,3775.2 C50_B.2@10625,3775.2 10632.72,3782.91 10670.21,3782.91 10687.29,3800 v1(10690,3800) ; R62_B.2@10801.77,3500.2 v1@10861.57,3500.2 ; R93_B.2@10926.77,3600.2 v1@10986.57,3600.2 ; C61_B.2@11025,3387.6 11026.3,3386.3 11083.7,3386.3 v1(11085,3385)
  other v1: 10861.67,3500.1 10986.67,3600.1 10490.1,3775.3 8596.12,3783.76 9435.91,3965 9385.91,4015 9435.91,4015
HV_P5V_C: C47_C.2 C49_C.2 C50_C.2 C51_C.2 C61_C.2 Q5_C.2 R62_C.2 R93_C.2 U15_C.3 U18_C.1 U21_C.5 U22_C.5 | length 970.6
  Top w15: U18_C.1@10550,6675.79 C49_C.2@10550,6775.2 ; U22_C.5@10950.59,6389.53 11006.91,6389.53 11008.66,6387.77 C61_C.2@11008.66,6379.13
  Top w20: v1(8596.12,6783.76) C51_C.2@8655.92,6783.76 ; U21_C.5@8657.95,6858.07 8657.84,6858.07 8656.02,6856.26 8656.02,6731.06 8727.24,6659.84 Q5_C.2@8856.02,6659.84 ; v1@10490.2,6775.2 C49_C.2@10550,6775.2 10673.66,6775.2 10688.47,6790 v1(10690,6790) ; R62_C.2@10801.77,6500.2 v1@10861.57,6500.2 ; R93_C.2@10926.77,6600.2 v1@10986.57,6600.2 ; C61_C.2@11025,6387.6 11026.3,6386.3 11083.7,6386.3 v1(11085,6385)
  other v1: 10861.67,6500.1 10986.67,6600.1 10490.1,6775.3 9435.91,6965 9385.91,7015 9435.91,7015
HV_P5V_D: C47_D.2 C49_D.2 C50_D.2 C51_D.2 C61_D.2 Q5_D.2 R62_D.2 R93_D.2 U15_D.3 U18_D.1 U21_D.5 U22_D.5 | length 967.7
  Top w15: U18_D.1@10550,9675.79 C49_D.2@10550,9775.2 ; U22_D.5@10950.59,9389.53 11006.91,9389.53 11008.66,9387.77 C61_D.2@11008.66,9379.13
  Top w20: v1(8596.12,9783.76) C51_D.2@8655.92,9783.76 ; U21_D.5@8657.95,9858.07 8657.84,9858.07 8656.02,9856.26 8656.02,9731.06 8727.24,9659.84 Q5_D.2@8856.02,9659.84 ; v1@10490.2,9775.2 10550,9775.2 10625,9775.2 10632.52,9782.72 10670.01,9782.72 10682.29,9795 v1(10685,9795) ; R62_D.2@10801.77,9500.2 v1@10861.57,9500.2 ; R93_D.2@10926.77,9600.2 v1@10986.57,9600.2 ; C61_D.2@11025,9387.6 11026.3,9386.3 11083.7,9386.3 v1(11085,9385)
  other v1: 10861.67,9500.1 10986.67,9600.1 10490.1,9775.3 9435.91,9965 9385.91,10015 9435.91,10015
HV_P12V_A: C16_A.2 C19_A.2 C21_A.2 C33_A.2 PS1_A.6 R61_A.2 U6_A.6 U15_A.1
  other v1: 9525,725 9625,725 9525,825 9625,825 8850,1400 8800,1450 8850,1450 8350,1800 8450,1800 8350,1900 8450,1900 8350,2000 8450,2000
HV_P12V_B: C16_B.2 C19_B.2 C21_B.2 C33_B.2 PS1_B.6 R61_B.2 U6_B.6 U15_B.1
  other v1: 9523.43,3708.66 9623.43,3708.66 9523.43,3808.66 9623.43,3808.66 9385.91,4365 9435.91,4365 9435.91,4415 8350,4800 8450,4800 8350,4900 8450,4900 8350,5000 8450,5000
HV_P12V_C: C16_C.2 C19_C.2 C21_C.2 C33_C.2 PS1_C.6 R61_C.2 U6_C.6 U15_C.1
  other v1: 9523.43,6708.66 9623.43,6708.66 9523.43,6808.66 9623.43,6808.66 9385.91,7365 9435.91,7365 9435.91,7415 8348.43,7783.66 8448.43,7783.66 8348.43,7883.66 8448.43,7883.66 8348.43,7983.66 8448.43,7983.66
HV_P12V_D: C16_D.2 C19_D.2 C21_D.2 C33_D.2 PS1_D.6 R61_D.2 U6_D.6 U15_D.1
  other v1: 9523.43,9708.66 9623.43,9708.66 9523.43,9808.66 9623.43,9808.66 9385.91,10365 9435.91,10365 9435.91,10415 8350,10800 8450,10800 8350,10900 8450,10900 8350,11000 8450,11000
I2C_SCL_3: J2.26
I2C_SDA_3: J2.22
IGB_TEMP_F_3: J3.57
INPUT-FAULT-RESET_1: R37.1 R38.1 R74_E.2 U14_E.1 | length 14975.4
  Top w10: R74_E.2@5552.19,11250.47 5584.53,11250.47 5598.31,11236.69 U14_E.1@5629.41,11236.69 5630,11237.28 5630,11273.73 5624.14,11279.59 5603.25,11279.59 v1(5602.83,11280)
  Top w15: R38.1@2200,639.37 R37.1@2300,639.37 2300,3005 3835,4540 3835,7665 2815,8685 2815,9935.47 2820,9940.47 v1(2820,11195)
  L5 - Plane/Horiz w15: v1(2820,11195) 4760,11195 5065,11500 5541.21,11500 5581.86,11459.36 5581.86,11433.14 5622.5,11392.5 5622.5,11343.59 5602.83,11323.93 v1(5602.83,11280)
INPUT_FET_LEFT_TEMP_F_3: J3.63
INPUT_FET_RIGHT_TEMP_F_3: J3.61
IPB1_BOARD_TEMP_3: J2.34 R33.2 | length 281.3
  Bottom w15: J2.34@2400,11700 2450,11650 R33.2@2450,11439.37
IPB1_CHA_CURRENT_SET_3: J2.1 R4.2 | length 160.6
  Top w15: R4.2@4000,11439.37 J2.1@4000,11600
IPB1_CHA_FET_EN_3: J2.21 R19.2 | length 160.6
  Top w15: R19.2@3000,11439.37 J2.21@3000,11600
IPB1_CHA_I_3: J3.15 R20.2 | length 280.7
  Bottom w15: J3.15@3300,300 3350,350 R20.2@3350,560
IPB1_CHA_RLY_EN_3: J2.17 R3.2 | length 160.6
  Top w15: R3.2@3200,11439.37 J2.17@3200,11600
IPB1_CHB_CURRENT_SET_3: J2.5 R8.2 | length 160.6
  Top w15: R8.2@3800,11439.37 J2.5@3800,11600
IPB1_CHB_FET_EN_3: J2.29 R23.2 | length 160.6
  Top w15: R23.2@2600,11439.37 J2.29@2600,11600
IPB1_CHB_I_3: J3.23 R24.2 | length 280.7
  Bottom w15: J3.23@2900,300 2950,350 R24.2@2950,560
IPB1_CHB_RLY_EN_3: J2.25 R7.2 | length 160.6
  Top w15: R7.2@2800,11439.37 J2.25@2800,11600
IPB1_CHC_CURRENT_SET_3: J2.9 R12.2 | length 160.6
  Top w15: R12.2@3600,11439.37 J2.9@3600,11600
IPB1_CHC_FET_EN_3: J2.37 R27.2 | length 160.6
  Top w15: R27.2@2200,11439.37 J2.37@2200,11600
IPB1_CHC_I_3: J3.31 R28.2 | length 280.7
  Bottom w15: J3.31@2500,300 2550,350 R28.2@2550,560
IPB1_CHC_RLY_EN_3: J2.33 R11.2 | length 160.6
  Top w15: R11.2@2400,11439.37 J2.33@2400,11600
IPB1_CHD_CURRENT_SET_3: J2.13 R16.2 | length 160.6
  Top w15: R16.2@3400,11439.37 J2.13@3400,11600
IPB1_CHD_FET_EN_3: J2.45 R31.2 | length 160.6
  Top w15: R31.2@1800,11439.37 J2.45@1800,11600
IPB1_CHD_I_3: J3.39 R32.2 | length 280.7
  Bottom w15: J3.39@2100,300 2150,350 R32.2@2150,560
IPB1_CHD_RLY_EN_3: J2.41 R15.2 | length 160.6
  Top w15: R15.2@2000,11439.37 J2.41@2000,11600
IPB1_RESET_3: J3.36 R37.2 | length 160.6
  Top w15: J3.36@2300,400 R37.2@2300,560.63
IPB2_BOARD_TEMP_3: J2.36 R36.2 | length 281.3
  Bottom w15: R36.2@2250,11439.37 2250,11650 J2.36@2300,11700
IPB2_CHA_CURRENT_SET_3: J2.3 R6.2 | length 160.6
  Top w15: R6.2@3900,11439.37 J2.3@3900,11600
IPB2_CHA_FET_EN_3: J2.23 R21.2 | length 160.6
  Top w15: R21.2@2900,11439.37 J2.23@2900,11600
IPB2_CHA_I_3: J3.19 R22.2 | length 280.7
  Bottom w15: J3.19@3100,300 3150,350 R22.2@3150,560
IPB2_CHA_RLY_EN_3: J2.19 R5.2 | length 160.6
  Top w15: R5.2@3100,11439.37 J2.19@3100,11600
IPB2_CHB_CURRENT_SET_3: J2.7 R10.2 | length 160.6
  Top w15: R10.2@3700,11439.37 J2.7@3700,11600
IPB2_CHB_FET_EN_3: J2.31 R25.2 | length 160.6
  Top w15: R25.2@2500,11439.37 J2.31@2500,11600
IPB2_CHB_I_3: J3.27 R26.2 | length 280.7
  Bottom w15: J3.27@2700,300 2750,350 R26.2@2750,560
IPB2_CHB_RLY_EN_3: J2.27 R9.2 | length 160.6
  Top w15: R9.2@2700,11439.37 J2.27@2700,11600
IPB2_CHC_CURRENT_SET_3: J2.11 R14.2 | length 160.6
  Top w15: R14.2@3500,11439.37 J2.11@3500,11600
IPB2_CHC_FET_EN_3: J2.39 R29.2 | length 160.6
  Top w15: R29.2@2100,11439.37 J2.39@2100,11600
IPB2_CHC_I_3: J3.35 R30.2 | length 280.7
  Bottom w15: J3.35@2300,300 2350,350 R30.2@2350,560
IPB2_CHC_RLY_EN_3: J2.35 R13.2 | length 160.6
  Top w15: R13.2@2300,11439.37 J2.35@2300,11600
IPB2_CHD_CURRENT_SET_3: J2.15 R18.2 | length 160.6
  Top w15: R18.2@3300,11439.37 J2.15@3300,11600
IPB2_CHD_FET_EN_3: J2.47 R34.2 | length 160.6
  Top w15: R34.2@1700,11439.37 J2.47@1700,11600
IPB2_CHD_I_3: J3.43 R35.2 | length 280.7
  Bottom w15: J3.43@1900,300 1950,350 R35.2@1950,560
IPB2_CHD_RLY_EN_3: J2.43 R17.2 | length 160.6
  Top w15: R17.2@1900,11439.37 J2.43@1900,11600
IPB2_RESET_3: J3.38 R38.2 | length 160.6
  Top w15: J3.38@2200,400 R38.2@2200,560.63
ISO_RTN_A: C19_A.1 C20_A.2 C21_A.1 C33_A.1 C47_A.1 C48_A.1 C49_A.1 C50_A.1 C51_A.1 C61_A.1 D6_A.2 D8_A.1 PS1_A.7 Q3_A.S1 Q3_A.S2 Q4_A.3 Q6_A.2 Q7_A.2 Q8_A.2 R61_A.1 R90_A.1 R98_A.1 R102_A.1 R104_A.2 U6_A.3 U6_A.4 U15_A.2 U15_A.4 U18_A.4 U18_A.8 U21_A.3 U22_A.3 | length 2034.1
  Top w12: R102_A.1@10686.02,1050 10760,1050 10775,1035 10775,825 10725,775 D8_A.1@10725,750 ; U18_A.8@10725.1,675.69 D8_A.1@10725.1,749.9
  Top w15: U21_A.3@8730.47,925.59 v1(8730.47,975.59) ; U18_A.4@10550,598.82 v1@10609.8,598.82 ; D8_A.1@10725,750 D8_A.1@10725.1,749.9 ; U18_A.8@10725.1,675.69 U18_A.8@10725.2,675.59 ; v1@10839.61,435.47 U22_A.3@10899.41,435.47
  Top w20: v1@8349.02,1090.2 Q4_A.3@8349.02,1150 ; v1(8732.4,750) C51_A.1@8732.4,800 v1(8782.4,800) ; Q7_A.2@8946.18,937.4 v1(8946.18,987.4) ; v1(9125,995) R90_A.1@9186.61,995 R90_A.1@9185.81,995.81 ; v1(9137.6,883.4) Q6_A.2@9187.6,883.4 ; v1(9166.34,500) U6_A.3@9166.34,550 ; v1@10290.2,575 R98_A.1@10350,575 ; v1(10490,850) 10490.1,849.9 10549.9,849.9 C49_A.1@10550,849.8 ; v1@10575.2,440.2 C48_A.1@10575.2,500 ; C50_A.1@10625,849.8 v1@10684.8,849.8 ; C61_A.1@11025,437.4 v1@11025,497.2
  Top w30: U15_A.2@9025,1430.91 9025,1575
  Top w50: Q3_A.S2@10495,2200 10495,2287.5 10732.09,2524.59 R104_A.2@10732.09,2675
  other v1: 9525,400 9625,400 10839.51,435.57 10575.1,440.1 11025.1,497.3 9525,500 9625,500 10290.1,575.1 10609.9,598.72 10249.9,775.1 10324.9,775.1 10249.9,850.1 10324.9,850.1 10684.9,849.7 8348.92,1090.1 9395,1625 9395,1675 9310,1680 9310,1735 9000,1900 9100,1900 9000,2000 9100,2000 9000,2100 9100,2100 9000,2200 9100,2200 9000,2300 9100,2300
ISO_RTN_B: C19_B.1 C20_B.2 C21_B.1 C33_B.1 C47_B.1 C48_B.1 C49_B.1 C50_B.1 C51_B.1 C61_B.1 D6_B.2 D8_B.1 PS1_B.7 Q3_B.S1 Q3_B.S2 Q4_B.3 Q6_B.2 Q7_B.2 Q8_B.2 R61_B.1 R90_B.1 R98_B.1 R102_B.1 R104_B.2 U6_B.3 U6_B.4 U15_B.2 U15_B.4 U18_B.4 U18_B.8 U21_B.3 U22_B.3 | length 2060.4
  Top w12: R102_B.1@10686.02,4050.2 10760,4050.2 10775,4035.2 10775,3825.2 10725,3775.2 D8_B.1@10725,3750.2 ; U18_B.8@10725.1,3675.89 D8_B.1@10725.1,3750.1
  Top w15: U21_B.3@8728.9,3909.25 v1(8728.9,3959.25) ; U18_B.4@10550,3599.02 v1@10609.8,3599.02 ; D8_B.1@10725,3750.2 D8_B.1@10725.1,3750.1 ; U18_B.8@10725.1,3675.89 U18_B.8@10725.2,3675.79 ; v1(10839.51,3435.77) 10841.56,3435.77 10855.79,3450 10898.78,3450 10899.41,3450.63 U22_B.3@10899.41,3460.47
  Top w20: v1@8349.02,4165.2 Q4_B.3@8349.02,4225 ; v1(8718.42,3728.66) 8720.29,3730.53 8720.29,3781.79 C51_B.1@8722.16,3783.66 ; C51_B.1@8730.83,3783.66 v1(8780.83,3783.66) ; v1(8933.42,3973.66) 8934.68,3972.4 8934.68,3922.32 Q7_B.2@8935.94,3921.06 ; v1(9123.42,3978.66) 9185.04,3978.66 R90_B.1@9184.23,3979.47 ; v1(9136.02,3867.07) Q6_B.2@9186.02,3867.07 ; v1(9164.76,3483.66) U6_B.3@9164.76,3533.66 ; v1@10290.2,3575.2 R98_B.1@10350,3575.2 ; v1(10490,3850.2) 10490.1,3850.1 10549.9,3850.1 C49_B.1@10550,3850 ; v1@10575.2,3440.39 C48_B.1@10575.2,3500.2 ; C50_B.1@10625,3850 v1@10684.8,3850 ; 11025,3437.6 v1@11025,3497.4
  Top w30: U15_B.2@9416.81,4190 9560.91,4190
  Top w50: Q3_B.S2@10495,5200 10495,5287.5 10732.09,5524.59 R104_B.2@10732.09,5675
  other v1: 9523.43,3383.66 9623.43,3383.66 10575.1,3440.3 9523.43,3483.66 9623.43,3483.66 11025.1,3497.5 10290.1,3575.3 10609.9,3598.92 10249.9,3775.3 10324.9,3775.3 10249.9,3850.3 10324.9,3850.3 10684.9,3849.9 9650,4025 8348.92,4165.1 9675,4325 9000,4900 9100,4900 9000,5000 9100,5000 9000,5100 9100,5100 9000,5200 9100,5200 9000,5300 9100,5300
ISO_RTN_C: C19_C.1 C20_C.2 C21_C.1 C33_C.1 C47_C.1 C48_C.1 C49_C.1 C50_C.1 C51_C.1 C61_C.1 D6_C.2 D8_C.1 PS1_C.7 Q3_C.S1 Q3_C.S2 Q4_C.3 Q6_C.2 Q7_C.2 Q8_C.2 R61_C.1 R90_C.1 R98_C.1 R102_C.1 R104_C.2 U6_C.3 U6_C.4 U15_C.2 U15_C.4 U18_C.4 U18_C.8 U21_C.3 U22_C.3 | length 2087.9
  Top w12: R102_C.1@10686.02,7050.2 10760,7050.2 10775,7035.2 10775,6825.2 10725,6775.2 D8_C.1@10725,6750.2 ; U18_C.8@10725.1,6675.89 D8_C.1@10725.1,6750.1
  Top w15: U21_C.3@8728.9,6909.25 v1(8728.9,6959.25) ; U18_C.4@10550,6599.02 v1@10609.8,6599.02 ; D8_C.1@10725,6750.2 D8_C.1@10725.1,6750.1 ; U18_C.8@10725.1,6675.89 U18_C.8@10725.2,6675.79 ; v1(10839.51,6435.77) 10841.56,6435.77 10855.79,6450 10898.78,6450 10899.41,6450.63 U22_C.3@10899.41,6460.47
  Top w20: v1@8349.02,7165.2 Q4_C.3@8349.02,7225 ; v1(8725,6720) 8726.91,6721.91 8726.91,6779.75 C51_C.1@8730.83,6783.66 v1(8780.83,6783.66) ; Q7_C.2@8944.6,6921.06 8944.8,6921.26 8944.8,6974.8 v1(8945,6975) ; v1(9120,6970) 9120.79,6970.79 9185.83,6970.79 R90_C.1@9186.61,6971.58 ; v1(9135,6855) 9185.88,6855 9186.02,6855.14 Q6_C.2@9186.02,6867.07 ; v1(9164.76,6483.66) U6_C.3@9164.76,6533.66 ; v1@10290.2,6575.2 R98_C.1@10350,6575.2 ; v1(10490,6850.2) 10490.1,6850.1 10549.9,6850.1 C49_C.1@10550,6850 ; v1@10575.2,6440.39 C48_C.1@10575.2,6500.2 ; C50_C.1@10625,6850 v1@10684.8,6850 ; 11025,6437.6 v1@11025,6497.4
  Top w30: U15_C.2@9416.81,7190 9560.91,7190
  Top w50: Q3_C.S2@10495,8200 10495,8287.5 10732.09,8524.59 R104_C.2@10732.09,8675
  other v1: 9523.43,6383.66 9623.43,6383.66 10575.1,6440.3 9523.43,6483.66 9623.43,6483.66 11025.1,6497.5 10290.1,6575.3 10609.9,6598.92 10249.9,6775.3 10324.9,6775.3 10249.9,6850.3 10324.9,6850.3 10684.9,6849.9 9650,7025 8348.92,7165.1 9675,7325 9000,7900 9100,7900 9000,8000 9100,8000 9000,8100 9100,8100 9000,8200 9100,8200 9000,8300 9100,8300
ISO_RTN_D: C19_D.1 C20_D.2 C21_D.1 C33_D.1 C47_D.1 C48_D.1 C49_D.1 C50_D.1 C51_D.1 C61_D.1 D6_D.2 D8_D.1 PS1_D.7 Q3_D.S1 Q3_D.S2 Q4_D.3 Q6_D.2 Q7_D.2 Q8_D.2 R61_D.1 R90_D.1 R98_D.1 R102_D.1 R104_D.2 U6_D.3 U6_D.4 U15_D.2 U15_D.4 U18_D.4 U18_D.8 U21_D.3 U22_D.3 | length 2086.9
  Top w12: R102_D.1@10686.02,10050.2 10760,10050.2 10775,10035.2 10775,9825.2 10725,9775.2 D8_D.1@10725,9750.2 ; U18_D.8@10725.1,9675.89 D8_D.1@10725.1,9750.1
  Top w15: U21_D.3@8728.9,9909.25 v1(8728.9,9959.25) ; U18_D.4@10550,9599.02 v1@10609.8,9599.02 ; D8_D.1@10725,9750.2 D8_D.1@10725.1,9750.1 ; U18_D.8@10725.1,9675.89 U18_D.8@10725.2,9675.79 ; v1(10839.51,9435.77) 10841.56,9435.77 10855.79,9450 10897.75,9450 10898.39,9450.63 U22_D.3@10898.39,9460.47
  Top w20: v1@8349.02,10165.2 Q4_D.3@8349.02,10225 ; v1(8725,9720) 8726.91,9721.91 8726.91,9779.75 C51_D.1@8730.83,9783.66 v1(8780.83,9783.66) ; Q7_D.2@8944.6,9921.06 8944.8,9921.26 8944.8,9974.8 v1(8945,9975) ; v1(9120,9970) 9120.79,9970.79 9185.83,9970.79 R90_D.1@9186.61,9971.58 ; v1(9135,9855) 9185.88,9855 9186.02,9855.14 Q6_D.2@9186.02,9867.07 ; v1(9164.76,9483.66) U6_D.3@9164.76,9533.66 ; v1@10290.2,9575.2 R98_D.1@10350,9575.2 ; v1(10490,9850.2) 10490.1,9850.1 10549.9,9850.1 C49_D.1@10550,9850 ; v1@10575.2,9440.39 C48_D.1@10575.2,9500.2 ; C50_D.1@10625,9850 v1@10684.8,9850 ; 11025,9437.6 v1@11025,9497.4
  Top w30: U15_D.2@9416.81,10190 9560.91,10190
  Top w50: Q3_D.S2@10495,11200 10495,11287.5 10732.09,11524.59 R104_D.2@10732.09,11675
  other v1: 9523.43,9383.66 9623.43,9383.66 10575.1,9440.3 9523.43,9483.66 9623.43,9483.66 11025.1,9497.5 10290.1,9575.3 10609.9,9598.92 10249.9,9775.3 10324.9,9775.3 10249.9,9850.3 10324.9,9850.3 10684.9,9849.9 9650,10025 8348.92,10165.1 9675,10325 9000,10900 9100,10900 9000,11000 9100,11000 9000,11100 9100,11100 9000,11200 9100,11200 9000,11300 9100,11300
